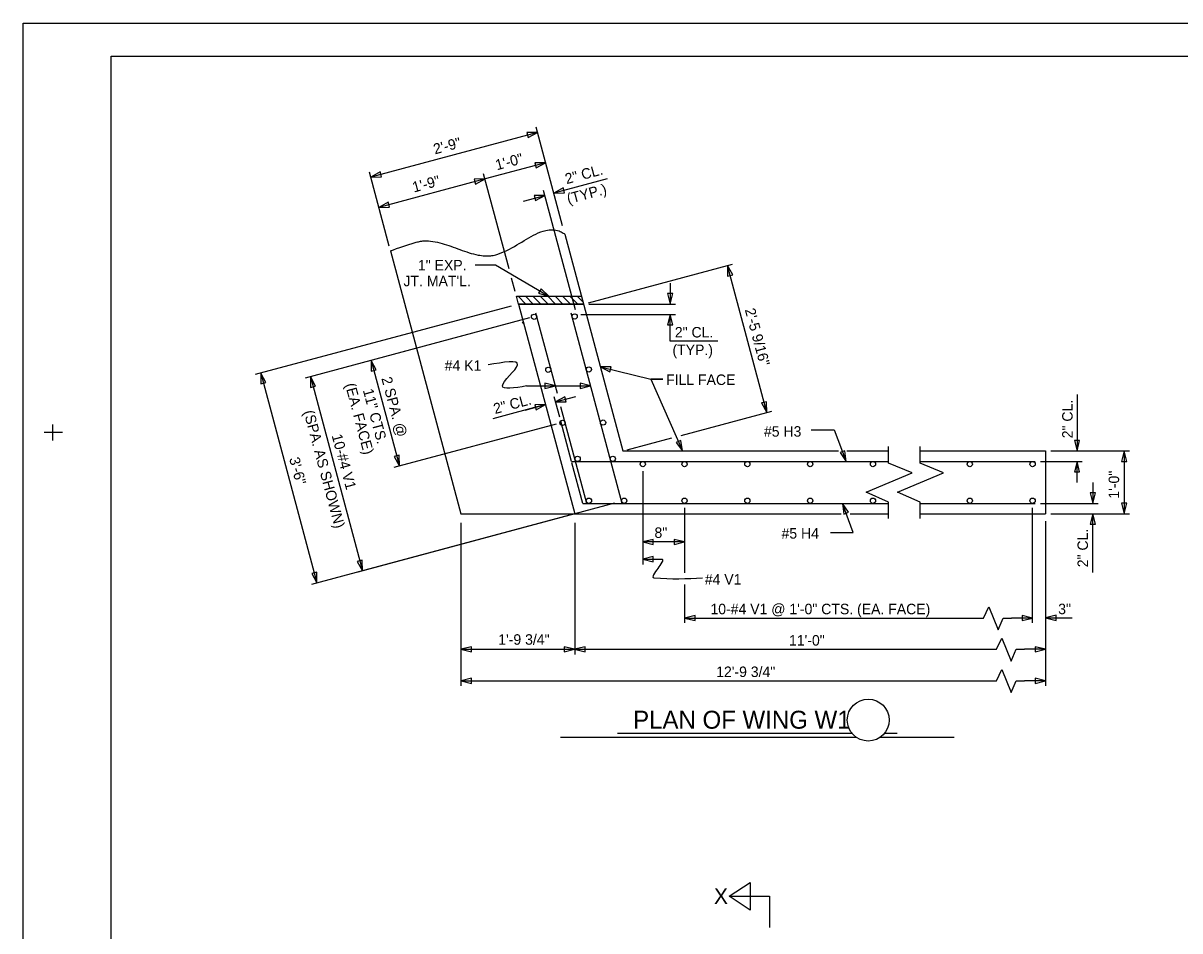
# Model space of a CAD drawing. Extents: x -41 to 191, y -168 to 6.
# Drawn here: x 0 to 18.42, y -84.01 to -69.56 of the extents above; entities that cross this region are included whole.
import ezdxf

# ---------------------------------------------------------------- set-up
doc = ezdxf.new("R2010")
doc.units = 0
for name, color, linetype in [('Arrowhead Terminators CELL', 7, 'Continuous'), ('Default', 7, 'Continuous'), ('Dimension Lines', 7, 'Continuous'), ('Mis Object Lines', 7, 'Continuous'), ('Plan Sheet CELL', 7, 'Continuous'), ('Plot Shape CELL', 7, 'Continuous'), ('Rebar K Bar Lines', 7, 'Continuous'), ('Rebar Lines', 7, 'Continuous'), ('Sub End Bent Cap Lines', 7, 'Continuous'), ('Sub End Bent Cap Lines CELL', 7, 'Continuous'), ('Subtitle Text', 7, 'Continuous'), ('Text', 7, 'Continuous'), ('Title Text', 7, 'Continuous'), ('User Information Notes CELL', 7, 'Continuous')]:
    doc.layers.add(name, color=color, linetype=linetype)

# ---------------------------------------------------------------- blocks, each defined once
blk = doc.blocks.new('SECSYM')
at = {"layer": 'Arrowhead Terminators CELL'}
blk.add_lwpolyline([(0, 0), (-2.48, 1.65), (-2.48, -1.65)], close=True, dxfattribs=at)
blk = doc.blocks.new('AH')
at = {"layer": 'Sub End Bent Cap Lines CELL'}
blk.add_lwpolyline([(0, 0), (-1.25, 0.31), (-1.25, -0.31)], close=True, dxfattribs=at)

msp = doc.modelspace()

# ---------------------------------------------------------------- linework, layer by layer
at = {"layer": 'Arrowhead Terminators CELL'}
for points in [[(8.191, -71.302), (8.02, -71.304), (8.042, -71.385)], [(8.321, -71.785), (8.15, -71.787), (8.171, -71.868)], [(5.535, -72.013), (5.706, -72.01), (5.685, -71.93)], [(7.355, -72.043), (7.184, -72.046), (7.205, -72.127)], [(8.45, -72.267), (8.622, -72.265), (8.6, -72.184)], [(8.308, -72.306), (8.137, -72.308), (8.158, -72.389)], [(5.665, -72.496), (5.836, -72.493), (5.814, -72.413)], [(11.216, -73.421), (11.219, -73.592), (11.299, -73.571)], [(8.373, -73.91), (8.251, -73.79), (8.208, -73.862)], [(10.305, -74.035), (10.346, -73.869), (10.263, -73.869)], [(10.305, -74.202), (10.263, -74.368), (10.346, -74.368)], [(5.541, -74.931), (5.543, -75.103), (5.624, -75.081)], [(3.783, -75.135), (3.786, -75.307), (3.867, -75.285)], [(9.192, -75.034), (9.343, -75.114), (9.363, -75.033)], [(4.575, -75.19), (4.578, -75.362), (4.658, -75.34)], [(8.475, -75.338), (8.309, -75.296), (8.309, -75.379)], [(9.036, -75.338), (8.869, -75.296), (8.869, -75.379)], [(8.479, -75.593), (8.65, -75.59), (8.628, -75.51)], [(8.318, -75.636), (8.146, -75.639), (8.168, -75.719)], [(11.843, -75.76), (11.84, -75.589), (11.76, -75.61)], [(10.502, -76.374), (10.473, -76.205), (10.397, -76.239)], [(5.991, -76.614), (5.988, -76.442), (5.908, -76.464)], [(13.108, -76.541), (13.087, -76.371), (13.01, -76.4)], [(13.048, -77.208), (13.067, -77.378), (13.145, -77.349)], [(9.867, -77.822), (10.033, -77.864), (10.033, -77.781)], [(10.533, -77.822), (10.367, -77.781), (10.367, -77.864)], [(9.867, -78.096), (10.033, -78.137), (10.033, -78.053)], [(5.403, -78.283), (5.4, -78.111), (5.32, -78.133)], [(4.678, -78.474), (4.675, -78.303), (4.595, -78.324)], [(10.533, -79.033), (10.7, -79.075), (10.7, -78.992)], [(16.075, -79.033), (15.908, -78.992), (15.908, -79.075)], [(16.282, -79.031), (16.448, -79.073), (16.448, -78.99)], [(6.972, -79.531), (7.138, -79.573), (7.138, -79.49)], [(8.782, -79.531), (8.616, -79.49), (8.616, -79.573)], [(8.782, -79.531), (8.948, -79.573), (8.948, -79.49)], [(16.282, -79.531), (16.116, -79.49), (16.116, -79.573)], [(6.973, -80.031), (7.139, -80.073), (7.139, -79.99)], [(16.282, -80.031), (16.116, -79.99), (16.116, -80.073)]]:
    msp.add_lwpolyline(points, close=True, dxfattribs=at)
at = {"layer": 'Default'}
for points in [[(13.781, -77.449), (13.781, -77.191), (13.424, -77.027), (14.156, -76.721), (13.781, -76.566), (13.781, -76.304)], [(14.283, -77.449), (14.283, -77.191), (13.926, -77.027), (14.658, -76.721), (14.283, -76.566), (14.283, -76.304)], [(15.165, -79.033), (15.294, -79.033), (15.376, -78.854), (15.529, -79.221), (15.606, -79.033), (15.738, -79.033)], [(15.372, -79.531), (15.501, -79.531), (15.583, -79.353), (15.736, -79.719), (15.814, -79.531), (15.945, -79.531)], [(15.372, -80.031), (15.501, -80.031), (15.583, -79.853), (15.736, -80.219), (15.814, -80.031), (15.945, -80.031)]]:
    msp.add_lwpolyline(points, dxfattribs=at)
at = {"layer": 'Dimension Lines'}
for p, q in [((8.59, -72.788), (8.17, -71.221)), ((8.191, -71.302), (5.535, -72.013)), ((8.321, -71.785), (7.355, -72.043)), ((5.829, -73.111), (5.514, -71.933)), ((7.738, -73.474), (7.333, -71.963)), ((7.355, -72.043), (5.665, -72.496)), ((9.302, -72.039), (8.45, -72.267)), ((7.967, -72.397), (8.308, -72.306)), ((8.796, -74.126), (8.287, -72.225)), ((9.004, -74.014), (11.296, -73.4)), ((11.843, -75.76), (11.216, -73.421)), ((7.835, -73.836), (7.778, -73.624)), ((10.305, -73.702), (10.305, -74.035)), ((8.007, -74.035), (7.882, -73.91)), ((8.124, -74.035), (7.999, -73.91)), ((8.242, -74.035), (8.117, -73.91)), ((8.36, -74.035), (8.235, -73.91)), ((8.478, -74.035), (8.353, -73.91)), ((8.596, -74.035), (8.471, -73.91)), ((8.714, -74.035), (8.589, -73.91)), ((8.831, -74.035), (8.706, -73.91)), ((8.915, -74.001), (8.824, -73.91)), ((9.007, -74.035), (10.388, -74.035)), ((7.771, -74.067), (3.697, -75.158)), ((8.879, -74.202), (10.388, -74.202)), ((10.305, -74.535), (10.305, -74.202)), ((8.066, -74.255), (4.489, -75.213)), ((8.066, -74.255), (5.615, -74.911)), ((7.974, -74.352), (7.948, -74.327)), ((10.305, -74.626), (10.305, -74.535)), ((11.062, -74.626), (10.305, -74.626)), ((5.541, -74.931), (5.991, -76.614)), ((3.783, -75.135), (4.678, -78.474)), ((4.575, -75.19), (5.403, -78.283)), ((8.018, -75.338), (8.475, -75.338)), ((8.458, -75.338), (9.036, -75.338)), ((8.544, -75.837), (8.457, -75.512)), ((8.479, -75.593), (8.801, -75.507)), ((16.783, -75.475), (16.783, -76.374)), ((8.318, -75.636), (7.482, -75.86)), ((7.996, -75.722), (8.318, -75.636)), ((10.481, -76.125), (11.923, -75.739)), ((8.487, -75.945), (5.905, -76.637)), ((12.551, -76.035), (12.914, -76.035)), ((12.914, -76.035), (13.108, -76.541)), ((9.619, -76.356), (10.332, -76.165)), ((16.367, -76.374), (17.617, -76.374)), ((16.367, -76.374), (16.72, -76.374)), ((17.533, -76.374), (17.533, -77.374)), ((16.2, -76.541), (16.867, -76.541)), ((16.783, -76.875), (16.783, -76.541)), ((9.867, -76.693), (9.867, -78.179)), ((17.033, -76.874), (17.033, -77.208)), ((9.418, -77.207), (5.332, -78.302)), ((10.533, -77.279), (10.533, -78.315)), ((13.22, -77.669), (13.048, -77.208)), ((16.075, -79.108), (16.075, -77.278)), ((16.2, -77.208), (17.117, -77.208)), ((8.703, -77.396), (4.592, -78.497)), ((6.972, -77.517), (6.972, -80.115)), ((8.783, -77.517), (8.783, -79.615)), ((16.282, -77.493), (16.282, -80.115)), ((16.367, -77.374), (17.617, -77.374)), ((16.367, -77.374), (17.009, -77.374)), ((17.033, -78.308), (17.033, -77.374)), ((12.857, -77.669), (13.22, -77.669)), ((10.533, -77.822), (9.867, -77.822)), ((10.533, -78.502), (10.533, -79.108)), ((10.533, -79.033), (15.165, -79.033)), ((16.075, -79.033), (15.738, -79.033)), ((16.282, -79.031), (16.707, -79.031)), ((6.972, -79.531), (8.782, -79.531)), ((8.782, -79.531), (15.372, -79.531)), ((16.282, -79.531), (15.945, -79.531)), ((6.972, -80.031), (15.372, -80.031)), ((16.282, -80.031), (15.945, -80.031)), ((11.245, -83.463), (11.888, -83.463)), ((11.888, -83.463), (11.888, -83.961))]:
    msp.add_line(p, q, dxfattribs=at)
for points in [[(7.197, -73.411), (7.524, -73.411), (8.373, -73.91)], [(9.192, -75.034), (9.994, -75.23), (10.187, -75.23)], [(10.187, -75.23), (9.994, -75.23), (10.502, -76.374)]]:
    msp.add_lwpolyline(points, dxfattribs=at)
msp.add_lwpolyline([(8.89, -73.91), (8.924, -74.035), (7.889, -74.035), (7.855, -73.91)], close=True, dxfattribs=at)
for points in [[(8.018, -75.338), (7.632, -75.338), (7.874, -75.005), (7.406, -75.005)], [(9.867, -78.096), (10.16, -78.095), (10.176, -78.098), (10.182, -78.108), (10.173, -78.142), (10.106, -78.244), (10.039, -78.347), (10.03, -78.381), (10.036, -78.39), (10.051, -78.394), (10.816, -78.394)]]:
    msp.add_spline(points, degree=3, dxfattribs=at)
at = {"layer": 'Mis Object Lines'}
msp.add_spline([(5.849, -73.186), (6.244, -73.056), (6.313, -73.038), (6.383, -73.03), (6.525, -73.037), (6.812, -73.115), (7.101, -73.217), (7.246, -73.254), (7.353, -73.268), (7.389, -73.269), (7.427, -73.268), (7.466, -73.263), (7.545, -73.245), (7.703, -73.181), (8.018, -73.001), (8.322, -72.864), (8.535, -72.871), (8.602, -72.905), (8.625, -72.921)], degree=3, dxfattribs=at)
at = {"layer": 'Plan Sheet CELL'}
for p, q in [((0, -69.563), (0, -69.563)), ((1.402, -70.087), (43.962, -70.087)), ((1.402, -98.017), (1.402, -70.087)), ((0.333, -76.072), (0.626, -76.072)), ((0.475, -76.206), (0.475, -75.953))]:
    msp.add_line(p, q, dxfattribs=at)
at = {"layer": 'Plot Shape CELL'}
msp.add_lwpolyline([(0, -69.563), (43.974, -69.563), (43.974, -98.823), (0, -98.823)], close=True, dxfattribs=at)
at = {"layer": 'Rebar K Bar Lines'}
for p, q in [((8.507, -75.459), (8.164, -74.178)), ((9.537, -77.208), (8.725, -74.178)), ((8.976, -77.208), (8.564, -75.669))]:
    msp.add_line(p, q, dxfattribs=at)
at = {"layer": 'Rebar Lines'}
for p, q in [((8.733, -76.541), (8.56, -75.897)), ((8.733, -76.541), (13.781, -76.541)), ((8.911, -77.208), (8.739, -76.564)), ((14.283, -76.541), (16.117, -76.541)), ((8.911, -77.208), (13.781, -77.208)), ((14.283, -77.208), (16.117, -77.208))]:
    msp.add_line(p, q, dxfattribs=at)
for centre in [(8.136, -74.237), (8.783, -74.232), (8.363, -75.081), (9.009, -75.076), (8.589, -75.926), (9.235, -75.921), (8.83, -76.499), (9.39, -76.499), (9.867, -76.583), (10.533, -76.583), (11.533, -76.583), (12.533, -76.583), (13.533, -76.583), (15.075, -76.583), (16.075, -76.583), (9.01, -77.166), (9.571, -77.166), (10.533, -77.166), (11.533, -77.166), (12.533, -77.166), (13.533, -77.166), (15.075, -77.166), (16.075, -77.166)]:
    msp.add_circle(centre, 0.0417, dxfattribs=at)
at = {"layer": 'Sub End Bent Cap Lines'}
for p, q in [((8.625, -72.921), (9.551, -76.374)), ((5.849, -73.186), (6.972, -77.374)), ((7.889, -74.035), (8.924, -74.035)), ((7.889, -74.035), (8.783, -77.374)), ((9.551, -76.374), (12.983, -76.374)), ((13.119, -76.374), (13.781, -76.374)), ((14.283, -76.374), (16.283, -76.374)), ((16.283, -76.374), (16.283, -77.374)), ((6.972, -77.374), (13.025, -77.374)), ((13.172, -77.374), (13.781, -77.374)), ((14.283, -77.374), (16.283, -77.374))]:
    msp.add_line(p, q, dxfattribs=at)
at = {"layer": 'Title Text'}
for p, q in [((8.557, -80.931), (13.266, -80.931)), ((9.467, -80.867), (13.198, -80.867)), ((13.65, -80.931), (14.825, -80.931)), ((13.722, -80.867), (13.92, -80.867))]:
    msp.add_line(p, q, dxfattribs=at)
msp.add_circle((13.458, -80.658), 0.334, dxfattribs=at)
at = {"layer": 'User Information Notes CELL'}
msp.add_line((1.402, -70.087), (1.402, -70.087), dxfattribs=at)

# ---------------------------------------------------------------- block references
at = {"layer": 'Arrowhead Terminators CELL', "xscale": 0.1336, "yscale": 0.1336}
for p, rotation in [((16.783, -76.374), -90), ((17.533, -76.374), 90), ((16.783, -76.541), 90), ((17.033, -77.208), -90), ((17.533, -77.374), -90), ((17.033, -77.374), 90)]:
    msp.add_blockref('AH', p, dxfattribs=dict(at, rotation=rotation))
at = {"layer": 'Dimension Lines', "xscale": 0.1331292, "yscale": -0.133130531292, "rotation": 180}
msp.add_blockref('SECSYM', (11.245, -83.463), dxfattribs=at)

# ---------------------------------------------------------------- texts
at = {"layer": 'Subtitle Text'}
msp.add_text('X', height=0.25, dxfattribs=at).set_placement((11.001, -83.586))
at = {"layer": 'Text'}
for s, rotation, p in [('2\'-9"', 15, (6.558, -71.653)), ('1\'-0"', 15, (7.545, -71.906)), ('1\'-9"', 15, (6.223, -72.26)), ('2" CL.', 15, (8.655, -72.127)), ('(TYP.)', 15, (8.684, -72.444)), ('2\'-5 9/16"', 285, (11.491, -74.125)), ('2" CL.', 360, (10.378, -74.567)), ('(TYP.)', 360, (10.34, -74.848)), ('(EA. FACE)', 285, (5.125, -75.317)), ('2 SPA. @', 285, (5.703, -75.217)), ('11" CTS.', 285, (5.409, -75.407)), ('2" CL.', 15, (7.515, -75.787)), ('2" CL.', 90, (16.713, -76.172)), ('(SPA. AS SHOWN)', 285, (4.465, -75.749)), ('10-#4 V1', 285, (4.912, -76.128)), ('3\'-6"', 285, (4.234, -76.496)), ('1\'-0"', 90, (17.453, -77.133)), ('8"', 360, (10.054, -77.757)), ('2" CL.', 90, (16.957, -78.225)), ('10-#4 V1 @ 1\'-0" CTS. (EA. FACE)', 360, (10.945, -78.973)), ('3"', 360, (16.483, -78.972))]:
    msp.add_text(s, height=0.167, rotation=rotation, dxfattribs=at).set_placement(p)
for s, p in [('1" EXP.', (6.287, -73.5)), ("JT. MAT'L.", (6.057, -73.751)), ('#4 K1', (6.713, -75.097)), ('FILL FACE', (10.238, -75.323)), ('#5 H3', (11.797, -76.146)), ('#5 H4', (12.077, -77.769)), ('#4 V1', (10.855, -78.501)), ('1\'-9 3/4"', (7.566, -79.458)), ('11\'-0"', (12.196, -79.472)), ('12\'-9 3/4"', (11.036, -79.972))]:
    msp.add_text(s, height=0.167, dxfattribs=at).set_placement(p)
at = {"layer": 'Title Text'}
msp.add_text('PLAN OF WING W1', height=0.2859, dxfattribs=at).set_placement((9.714, -80.795))

doc.saveas('drawing.dxf')
